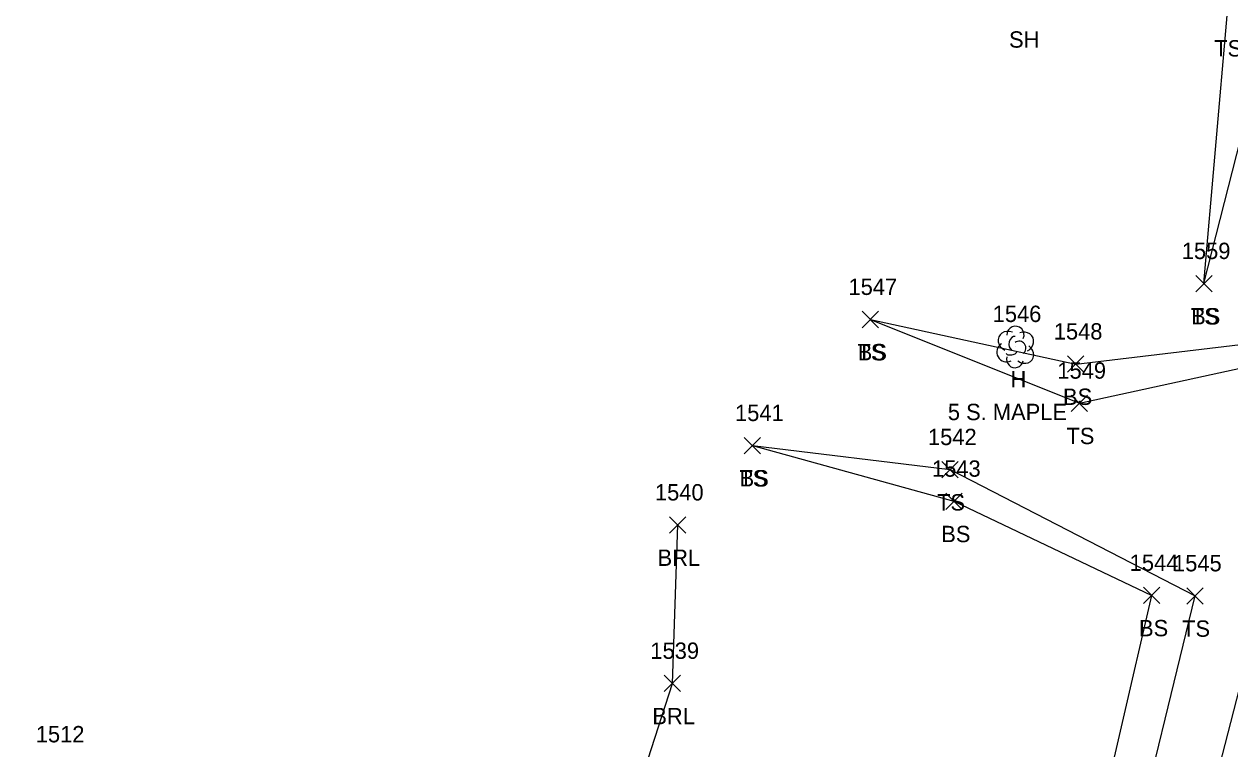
# Model space of a CAD drawing. Extents: x 1654425 to 1656893, y 667839 to 678429.
# Drawn here: x 1654478.4 to 1654625.8, y 668529.4 to 668618 of the extents above; entities that cross this region are included whole.
import ezdxf

# ---------------------------------------------------------------- set-up
doc = ezdxf.new("R2010")
doc.units = 0
for name, color, linetype in [('L_A', 7, 'Continuous'), ('L_C', 7, 'Continuous'), ('L_I', 7, 'Continuous'), ('L_TIC', 7, 'Continuous'), ('LABL', 7, 'Continuous'), ('LELB', 7, 'Continuous'), ('LTD', 7, 'Continuous'), ('PET', 7, 'Continuous')]:
    doc.layers.add(name, color=color, linetype=linetype)

msp = doc.modelspace()

# ---------------------------------------------------------------- linework, layer by layer
at = {"layer": 'L_TIC'}
for points in [[(1654621.64, 668585.29), (1654623.64, 668587.29)], [(1654623.64, 668585.29), (1654621.64, 668587.29)], [(1654621.64, 668585.29), (1654623.64, 668587.29)], [(1654623.64, 668585.29), (1654621.64, 668587.29)], [(1654580.88, 668580.9), (1654582.88, 668582.9)], [(1654582.88, 668580.9), (1654580.88, 668582.9)], [(1654580.88, 668580.9), (1654582.88, 668582.9)], [(1654582.88, 668580.9), (1654580.88, 668582.9)], [(1654605.98, 668575.45), (1654607.98, 668577.45)], [(1654607.98, 668575.45), (1654605.98, 668577.45)], [(1654606.43, 668570.66), (1654608.43, 668572.66)], [(1654608.43, 668570.66), (1654606.43, 668572.66)], [(1654566.44, 668565.48), (1654568.44, 668567.48)], [(1654568.44, 668565.48), (1654566.44, 668567.48)], [(1654566.44, 668565.48), (1654568.44, 668567.48)], [(1654568.44, 668565.48), (1654566.44, 668567.48)], [(1654590.61, 668562.54), (1654592.61, 668564.54)], [(1654592.61, 668562.54), (1654590.61, 668564.54)], [(1654591.09, 668558.67), (1654593.09, 668560.67)], [(1654593.09, 668558.67), (1654591.09, 668560.67)], [(1654557.31, 668555.77), (1654559.31, 668557.77)], [(1654559.31, 668555.77), (1654557.31, 668557.77)], [(1654615.27, 668547.16), (1654617.27, 668549.16)], [(1654617.27, 668547.16), (1654615.27, 668549.16)], [(1654615.27, 668547.16), (1654617.27, 668549.16)], [(1654617.27, 668547.16), (1654615.27, 668549.16)], [(1654620.57, 668547.1), (1654622.57, 668549.1)], [(1654622.57, 668547.1), (1654620.57, 668549.1)], [(1654620.57, 668547.1), (1654622.57, 668549.1)], [(1654622.57, 668547.1), (1654620.57, 668549.1)], [(1654556.67, 668536.4), (1654558.67, 668538.4)], [(1654558.67, 668536.4), (1654556.67, 668538.4)]]:
    msp.add_lwpolyline(points, dxfattribs=at)
at = {"layer": 'LABL'}
msp.add_lwpolyline([(1654481.96, 668527.19), (1654519.46, 668513.68), (1654552.15, 668520.24), (1654557.67, 668537.4), (1654558.31, 668556.77)], dxfattribs=at)
at = {"layer": 'LELB'}
for points in [[(1654581.88, 668581.9), (1654606.98, 668576.45), (1654627.8, 668578.91), (1654641.17, 668616.39), (1654649.87, 668649.23), (1654649.52, 668665.58), (1654651.97, 668671.89), (1654662.51, 668696.29), (1654672.37, 668724.45), (1654685.62, 668761.8), (1654697.84, 668800.3), (1654711.19, 668841.94), (1654722.77, 668879.71)], [(1654622.64, 668586.29), (1654631.18, 668619.85), (1654637.57, 668649.9), (1654638.19, 668671.12), (1654637.91, 668695.82)], [(1654622.64, 668586.29), (1654625.49, 668619.06), (1654630.92, 668654.48), (1654630.28, 668672.04)], [(1654581.88, 668581.9), (1654607.43, 668571.66), (1654629.53, 668576.46), (1654643.54, 668615.31), (1654655.17, 668648.77)], [(1654567.44, 668566.48), (1654592.09, 668559.67), (1654616.27, 668548.16)], [(1654567.44, 668566.48), (1654591.61, 668563.54), (1654621.57, 668548.1)], [(1654478.4, 668520.24), (1654524.92, 668504.49), (1654554.63, 668495.51), (1654575.92, 668488.4), (1654582.62, 668487.53), (1654594.71, 668489.65), (1654606.09, 668498.04), (1654613.45, 668514.77), (1654621.57, 668548.1)], [(1654478.94, 668522.02), (1654523, 668507.7), (1654554.1, 668496.3), (1654576.79, 668490.74), (1654583, 668489.45), (1654594.74, 668491.66), (1654603.26, 668500.01), (1654608.84, 668516.04), (1654616.27, 668548.16)]]:
    msp.add_lwpolyline(points, dxfattribs=at)
at = {"layer": 'LTD'}
msp.add_line((1654599.56, 668578.59), (1654599.56, 668578.59), dxfattribs=at)
msp.add_line((1654599.56, 668578.59), (1654599.56, 668578.59), dxfattribs=at)
msp.add_arc((1654599.61, 668580.02), 1.05, 335.5272, 180.9563, dxfattribs=at)
for centre, major_axis, ratio, start_param, end_param in [((1654598.77, 668579.25), (1.21, -0.51), 0.895232, 1.570796, 4.712389), ((1654600.61, 668579.17), (-1.14, -0.48), 0.949671, 1.570796, 4.712389), ((1654599.36, 668579.04), (-0.208, -0.792), 0.645439, 3.141593, 6.283185), ((1654600.06, 668578.42), (-0.5, 0.667), 0.989748, 3.141593, 6.283185), ((1654598.48, 668577.88), (0.58, -1.04), 0.959034, 3.141593, 6.283185), ((1654599.11, 668577.84), (-0.625, -0.083), 0.423636, 0, 3.141593), ((1654600.56, 668577.75), (-1.09, 0.79), 0.841452, 1.570796, 4.712389), ((1654599.56, 668577.09), (0.26, 1.06), 0.942809, 1.570796, 4.712389)]:
    msp.add_ellipse(centre, major_axis=major_axis, ratio=ratio, start_param=start_param, end_param=end_param, dxfattribs=at)
at = {"layer": 'PET'}
msp.add_lwpolyline([(1654621.12, 668380.08), (1654605.24, 668384.01), (1654589.51, 668387.16), (1654598.99, 668428.03), (1654608.32, 668463.46), (1654620, 668509.52), (1654636.49, 668573.63), (1654648.24, 668612.9), (1654659.58, 668647.93)], dxfattribs=at)

# ---------------------------------------------------------------- texts
at = {"layer": 'L_A'}
for s, p in [('SH', (1654598.82, 668615.14)), ('TS', (1654623.9, 668614.06)), ('TS', (1654621.05, 668581.29)), ('BS', (1654621.08, 668581.29)), ('TS', (1654580.29, 668576.9)), ('BS', (1654580.32, 668576.9)), ('H', (1654599, 668573.59)), ('BS', (1654605.42, 668571.45)), ('TS', (1654605.84, 668566.66)), ('TS', (1654565.85, 668561.48)), ('BS', (1654565.88, 668561.48)), ('TS', (1654590.02, 668558.54)), ('BS', (1654590.53, 668554.67)), ('BRL', (1654555.85, 668551.77)), ('BS', (1654614.71, 668543.16)), ('BS', (1654614.71, 668543.16)), ('TS', (1654619.98, 668543.1)), ('TS', (1654619.98, 668543.1)), ('BRL', (1654555.21, 668532.4))]:
    msp.add_text(s, height=2, dxfattribs=at).set_placement(p)
at = {"layer": 'L_C'}
msp.add_text('5 S. MAPLE', height=2, dxfattribs=at).set_placement((1654591.34, 668569.59))
at = {"layer": 'L_I'}
for s, p in [('1559', (1654619.94, 668589.29)), ('1559', (1654619.94, 668589.29)), ('1547', (1654579.19, 668584.9)), ('1547', (1654579.19, 668584.9)), ('1546', (1654596.82, 668581.59)), ('1548', (1654604.29, 668579.45)), ('1549', (1654604.73, 668574.66)), ('1541', (1654565.32, 668569.48)), ('1541', (1654565.32, 668569.48)), ('1542', (1654588.91, 668566.54)), ('1543', (1654589.4, 668562.67)), ('1540', (1654555.53, 668559.77)), ('1544', (1654613.57, 668551.16)), ('1544', (1654613.57, 668551.16)), ('1545', (1654618.87, 668551.1)), ('1545', (1654618.87, 668551.1)), ('1539', (1654554.97, 668540.4)), ('1512', (1654479.83, 668530.19))]:
    msp.add_text(s, height=2, dxfattribs=at).set_placement(p)

doc.saveas('drawing.dxf')
